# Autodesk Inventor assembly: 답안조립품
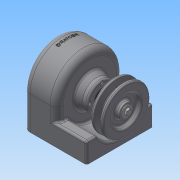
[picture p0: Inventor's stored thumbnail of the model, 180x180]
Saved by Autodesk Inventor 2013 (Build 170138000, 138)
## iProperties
Created: 2015-02
Part Number: 답안조립품
Document SubType Name: Assembly
Designer: Administrator
Author: Administrator
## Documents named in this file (14)
- C:\Documents and Settings\Administrator\바탕 화면\450214V1001\답안조립품.iam
- C:\Documents and Settings\Administrator\바탕 화면\450214V1001\1-본체.ipt
- C:\Documents and Settings\Administrator\바탕 화면\450214V1001\베어링 6001.ipt
- C:\Documents and Settings\Administrator\바탕 화면\450214V1001\축.ipt
- C:\Documents and Settings\Administrator\바탕 화면\450214V1001\키5x5.ipt
- C:\Documents and Settings\Administrator\바탕 화면\450214V1001\5-스퍼기어.ipt
- C:\Documents and Settings\Administrator\바탕 화면\450214V1001\오일실.ipt
- C:\Documents and Settings\Administrator\바탕 화면\450214V1001\축커버.ipt
- C:\Documents and Settings\Administrator\바탕 화면\450214V1001\M3x0.5.ipt
- C:\Documents and Settings\Administrator\바탕 화면\450214V1001\키4x4.ipt
- C:\Documents and Settings\Administrator\바탕 화면\450214V1001\4-벨트풀리.ipt
- C:\Documents and Settings\Administrator\바탕 화면\450214V1001\와샤.ipt
- C:\Documents and Settings\Administrator\바탕 화면\450214V1001\M5x0.8.ipt
- M5x0.8.ipt
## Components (7 placed, 4 different names)
1. 1-본체:1
2. 4-벨트풀리:1 — 플러쉬:3, 각도:4
3. M5x0.8:1
4. M3x0.5:1
5. M3x0.5:2
6. M3x0.5:3
7. M3x0.5:4
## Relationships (2: Flush 1, Angle 1)
- 플러쉬:3 [Flush]: 4-벨트풀리:1
- 각도:4 [Angle]: 4-벨트풀리:1
